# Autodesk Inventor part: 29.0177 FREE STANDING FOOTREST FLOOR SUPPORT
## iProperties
Created: 2007-06
Part Number: 29.0177 FREE STANDING FOOTREST FLOOR SUPPORT
Material: Aluminum-6061
Document SubType Name: Modeling
Designer: Andy Moles
Density: 2.71 g/cm^3
Author: Andy Moles
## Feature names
1. Extrusion1
2. Hole1
